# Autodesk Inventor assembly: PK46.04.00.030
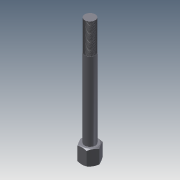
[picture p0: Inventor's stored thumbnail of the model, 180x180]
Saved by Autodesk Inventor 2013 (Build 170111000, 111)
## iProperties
Created: 2005-04
Part Number: PK46.04.00.030
Document SubType Name: Assembly
Designer: salex
Manufacturer: Standard
Standards Organization: Custom
Author: salex
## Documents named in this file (3)
- D:\FrontLoaderVault\Data\Assy, Chassis, Front\PK46.04.00.030.iam
- D:\FrontLoaderVault\Data\Assy, Chassis, Front\027.15.22.127.ipt
- D:\FrontLoaderVault\Data\Assy, Chassis, Front\027.13.14.227.ipt
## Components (2 placed, 2 different names)
1. 027.15.22.127:1 — Insert:1
2. 027.13.14.227:1 — Insert:1
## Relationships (1: Insert 1)
- Insert:1: 027.15.22.127:1 ↔ 027.13.14.227:1
